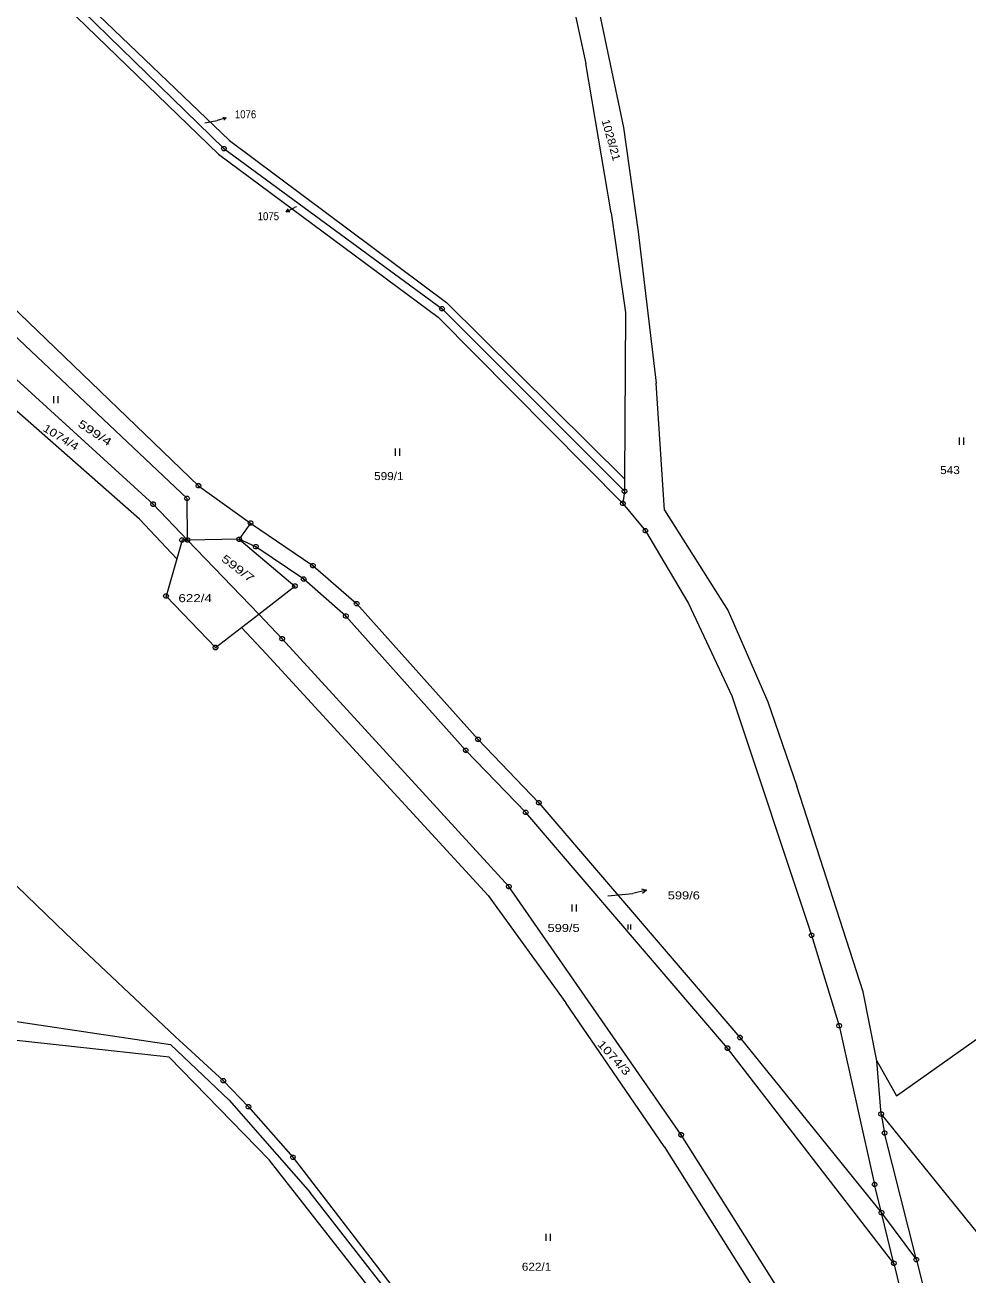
# Model space of a CAD drawing. Extents: x -687390 to -684106, y -954833 to -951648.
# Drawn here: x -686876.1 to -686675.9, y -953282.2 to -953016.7 of the extents above; entities that cross this region are included whole.
import ezdxf
from ezdxf.enums import TextEntityAlignment as Align

# ---------------------------------------------------------------- set-up
doc = ezdxf.new("R2010")
doc.units = 0
doc.header["$LTSCALE"] = 0.68
for name, color, linetype, lineweight in [('1', 7, 'Continuous', 13), ('3', 7, 'Continuous', 13), ('7', 7, 'Continuous', 13), ('8', 7, 'Continuous', 13)]:
    doc.layers.add(name, color=color, linetype=linetype, lineweight=lineweight)
doc.layers.add('2', color=7, linetype='Continuous')

msp = doc.modelspace()

# ---------------------------------------------------------------- linework, layer by layer
at = {"layer": '1'}
for p, q in [((-686764.18, -952991.34), (-686757.06, -953024.89)), ((-686751.65, -953056.55), (-686757.06, -953024.89)), ((-686751.65, -953056.55), (-686748.65, -953077.73)), ((-686745.94, -953060.65), (-686742.13, -953092.77)), ((-686786.65, -953075.62), (-686748.8, -953113.06)), ((-686878.63, -953082.32), (-686841.73, -953117.26)), ((-686848.93, -953118.48), (-686882.52, -953087.82)), ((-686851.84, -953121.63), (-686885.49, -953092.02)), ((-686740.36, -953119.73), (-686742.13, -953092.77)), ((-686841.63, -953126.08), (-686848.93, -953118.48)), ((-686851.84, -953121.63), (-686843.92, -953130.06)), ((-686826.51, -953141.84), (-686841.63, -953126.08)), ((-686826.51, -953141.84), (-686818.81, -953135.86)), ((-686826.51, -953141.84), (-686821.51, -953147.06)), ((-686830.2, -953144.68), (-686824.95, -953150.28)), ((-686777.81, -953201.6), (-686824.95, -953150.28)), ((-686718.37, -953160.43), (-686712.21, -953178.37)), ((-686691.08, -953244.15), (-686578.63, -953164.25)), ((-686698.16, -953222.08), (-686712.21, -953178.37)), ((-686897.44, -953180.91), (-686867.52, -953209.56)), ((-686777.81, -953201.6), (-686761.29, -953224.39)), ((-686844.28, -953231.53), (-686867.52, -953209.56)), ((-686695.24, -953236.73), (-686698.16, -953222.08)), ((-686740.37, -953254.88), (-686761.29, -953224.39)), ((-686834.02, -953240.95), (-686844.28, -953231.53)), ((-686845.52, -953235.93), (-686824.32, -953257.77)), ((-686694.31, -953248.02), (-686693.59, -953252.06)), ((-686686.85, -953278.95), (-686693.59, -953252.06)), ((-686740.37, -953254.88), (-686675.95, -953357.39)), ((-686781.85, -953311.83), (-686824.32, -953257.77)), ((-686694.24, -953268.98), (-686695.71, -953262.97)), ((-686773.57, -953318.57), (-686815.59, -953264.66)), ((-686694.24, -953268.98), (-686686.85, -953278.95)), ((-686691.61, -953279.73), (-686694.24, -953268.98)), ((-686686.85, -953278.95), (-686682.37, -953296.8))]:
    msp.add_line(p, q, dxfattribs=at)
for points in [[(-686903.71, -952971.16), (-686874.76, -953003.02), (-686833.89, -953042.95), (-686787.58, -953076.97), (-686748.81, -953115.73), (-686749.19, -953118.31), (-686744.38, -953124.12), (-686735.23, -953139.57), (-686726.05, -953159.19), (-686709.09, -953210.04), (-686703.22, -953229.26), (-686695.71, -953262.97)], [(-686757.01, -953000.39), (-686749.02, -953038.47), (-686745.94, -953060.65)], [(-686876.02, -953004.42), (-686835.02, -953044.1), (-686788.37, -953078.75), (-686749.19, -953118.31)], [(-686868.78, -953006.67), (-686832.75, -953041.23), (-686786.65, -953075.62)], [(-686929.03, -953026.05), (-686928.66, -953028.62), (-686839.29, -953114.56), (-686828.23, -953122.48), (-686830.67, -953125.93)], [(-686748.65, -953077.73), (-686748.8, -953113.06), (-686748.81, -953115.73)], [(-686830.67, -953125.93), (-686841.63, -953126.08), (-686841.73, -953117.26)], [(-686740.36, -953119.73), (-686726.84, -953141.16), (-686718.37, -953160.43)], [(-686828.23, -953122.48), (-686815, -953131.52), (-686805.71, -953139.6), (-686779.94, -953168.43), (-686767.01, -953181.9), (-686724.31, -953231.77), (-686694.24, -953268.98)], [(-686841.63, -953126.08), (-686842.79, -953126.1), (-686843.92, -953130.06), (-686846.19, -953137.99), (-686835.68, -953148.93), (-686830.2, -953144.68), (-686826.51, -953141.84)], [(-686691.61, -953279.73), (-686726.95, -953234.04), (-686769.81, -953183.96), (-686782.54, -953170.76), (-686808.01, -953142.23), (-686816.95, -953134.39), (-686827.13, -953127.51), (-686830.67, -953125.93), (-686818.81, -953135.86)], [(-686691.61, -953279.73), (-686685.79, -953303.59), (-686677.39, -953346.66), (-686736.8, -953252.45), (-686773.39, -953199.71), (-686821.51, -953147.06)], [(-686845.52, -953235.93), (-686887.1, -953231.37), (-686910.01, -953225.72), (-686942.38, -953198.97)], [(-686907.28, -953222.77), (-686897.88, -953225.38), (-686845.22, -953233.23), (-686832.78, -953245.07), (-686815.59, -953264.66)], [(-686694.31, -953248.02), (-686695.24, -953236.73), (-686691.08, -953244.15)], [(-686834.02, -953240.95), (-686828.66, -953246.47), (-686819.24, -953257.21), (-686798.48, -953284.2), (-686785.18, -953302.55), (-686773.57, -953318.57)], [(-686694.31, -953248.02), (-686654.73, -953296.99), (-686579.98, -953373.97), (-686534.21, -953420.02), (-686500.91, -953457.57), (-686468.1, -953494.74)]]:
    msp.add_lwpolyline(points, dxfattribs=at)
at = {"layer": '3'}
for p, q in [((-686870.07, -953095.51), (-686870.07, -953097.01)), ((-686869.07, -953097.01), (-686869.07, -953095.51)), ((-686677.79, -953104.33), (-686677.79, -953105.83)), ((-686676.79, -953105.83), (-686676.79, -953104.33)), ((-686797.54, -953106.67), (-686797.54, -953108.17)), ((-686796.54, -953108.17), (-686796.54, -953106.67)), ((-686760.01, -953203.49), (-686760.01, -953204.99)), ((-686759.01, -953204.99), (-686759.01, -953203.49)), ((-686748.155, -953207.785), (-686748.155, -953208.79)), ((-686747.485, -953208.79), (-686747.485, -953207.785)), ((-686765.51, -953273.43), (-686765.51, -953274.93)), ((-686764.51, -953274.93), (-686764.51, -953273.43))]:
    msp.add_line(p, q, dxfattribs=at)
at = {"layer": '7'}
for p, q in [((-686837.93, -953037.43), (-686835.33, -953036.99)), ((-686833.413, -953036.385), (-686835.33, -953036.99)), ((-686820.653, -953056.376), (-686818.88, -953055.43)), ((-686818.55, -953055.3), (-686818.88, -953055.43)), ((-686752.35, -953201.64), (-686747.08, -953201.14)), ((-686744.164, -953200.437), (-686747.08, -953201.14))]:
    msp.add_line(p, q, dxfattribs=at)
for points in [[(-686834.153, -953036.267), (-686833.413, -953036.385), (-686833.951, -953036.906)], [(-686819.904, -953056.356), (-686820.653, -953056.376), (-686820.22, -953055.765)], [(-686745.253, -953200.185), (-686744.164, -953200.437), (-686745.019, -953201.157)]]:
    msp.add_lwpolyline(points, dxfattribs=at)
at = {"layer": '8'}
for p, q in [((-686834.01, -953042.95), (-686833.77, -953042.95)), ((-686787.7, -953076.97), (-686787.46, -953076.97)), ((-686839.41, -953114.56), (-686839.17, -953114.56)), ((-686841.85, -953117.26), (-686841.61, -953117.26)), ((-686748.93, -953115.73), (-686748.69, -953115.73)), ((-686849.05, -953118.48), (-686848.81, -953118.48)), ((-686749.31, -953118.31), (-686749.07, -953118.31)), ((-686828.35, -953122.48), (-686828.11, -953122.48)), ((-686744.5, -953124.12), (-686744.26, -953124.12)), ((-686842.91, -953126.1), (-686842.67, -953126.1)), ((-686841.75, -953126.08), (-686841.51, -953126.08)), ((-686830.79, -953125.93), (-686830.55, -953125.93)), ((-686827.25, -953127.51), (-686827.01, -953127.51)), ((-686815.12, -953131.52), (-686814.88, -953131.52)), ((-686818.93, -953135.86), (-686818.69, -953135.86)), ((-686817.07, -953134.39), (-686816.83, -953134.39)), ((-686846.31, -953137.99), (-686846.07, -953137.99)), ((-686805.83, -953139.6), (-686805.59, -953139.6)), ((-686808.13, -953142.23), (-686807.89, -953142.23)), ((-686821.63, -953147.06), (-686821.39, -953147.06)), ((-686835.8, -953148.93), (-686835.56, -953148.93)), ((-686782.66, -953170.76), (-686782.42, -953170.76)), ((-686780.06, -953168.43), (-686779.82, -953168.43)), ((-686769.93, -953183.96), (-686769.69, -953183.96)), ((-686767.13, -953181.9), (-686766.89, -953181.9)), ((-686773.51, -953199.71), (-686773.27, -953199.71)), ((-686709.21, -953210.04), (-686708.97, -953210.04)), ((-686703.34, -953229.26), (-686703.1, -953229.26)), ((-686724.43, -953231.77), (-686724.19, -953231.77)), ((-686727.07, -953234.04), (-686726.83, -953234.04)), ((-686834.14, -953240.95), (-686833.9, -953240.95)), ((-686828.78, -953246.47), (-686828.54, -953246.47)), ((-686694.43, -953248.02), (-686694.19, -953248.02)), ((-686736.92, -953252.45), (-686736.68, -953252.45)), ((-686693.71, -953252.06), (-686693.47, -953252.06)), ((-686819.36, -953257.21), (-686819.12, -953257.21)), ((-686695.83, -953262.97), (-686695.59, -953262.97)), ((-686694.36, -953268.98), (-686694.12, -953268.98)), ((-686691.73, -953279.73), (-686691.49, -953279.73)), ((-686686.97, -953278.95), (-686686.73, -953278.95))]:
    msp.add_line(p, q, dxfattribs=at)
for points in [[(-686833.74, -953042.47), (-686833.49, -953042.65), (-686833.39, -953042.94), (-686833.49, -953043.23), (-686833.74, -953043.41), (-686834.05, -953043.41), (-686834.3, -953043.23), (-686834.4, -953042.94), (-686834.3, -953042.65), (-686834.05, -953042.47)], [(-686787.43, -953076.49), (-686787.18, -953076.67), (-686787.08, -953076.96), (-686787.18, -953077.25), (-686787.43, -953077.43), (-686787.74, -953077.43), (-686787.99, -953077.25), (-686788.09, -953076.96), (-686787.99, -953076.67), (-686787.74, -953076.49)], [(-686839.14, -953114.08), (-686838.89, -953114.26), (-686838.79, -953114.55), (-686838.89, -953114.84), (-686839.14, -953115.02), (-686839.45, -953115.02), (-686839.7, -953114.84), (-686839.8, -953114.55), (-686839.7, -953114.26), (-686839.45, -953114.08)], [(-686748.66, -953115.25), (-686748.41, -953115.43), (-686748.31, -953115.72), (-686748.41, -953116.01), (-686748.66, -953116.19), (-686748.97, -953116.19), (-686749.22, -953116.01), (-686749.32, -953115.72), (-686749.22, -953115.43), (-686748.97, -953115.25)], [(-686841.58, -953116.78), (-686841.33, -953116.96), (-686841.23, -953117.25), (-686841.33, -953117.54), (-686841.58, -953117.72), (-686841.89, -953117.72), (-686842.14, -953117.54), (-686842.24, -953117.25), (-686842.14, -953116.96), (-686841.89, -953116.78)], [(-686749.04, -953117.83), (-686748.79, -953118.01), (-686748.69, -953118.3), (-686748.79, -953118.59), (-686749.04, -953118.77), (-686749.35, -953118.77), (-686749.6, -953118.59), (-686749.7, -953118.3), (-686749.6, -953118.01), (-686749.35, -953117.83)], [(-686848.78, -953118), (-686848.53, -953118.18), (-686848.43, -953118.47), (-686848.53, -953118.76), (-686848.78, -953118.94), (-686849.09, -953118.94), (-686849.34, -953118.76), (-686849.44, -953118.47), (-686849.34, -953118.18), (-686849.09, -953118)], [(-686828.08, -953122), (-686827.83, -953122.18), (-686827.73, -953122.47), (-686827.83, -953122.76), (-686828.08, -953122.94), (-686828.39, -953122.94), (-686828.64, -953122.76), (-686828.74, -953122.47), (-686828.64, -953122.18), (-686828.39, -953122)], [(-686842.64, -953125.62), (-686842.39, -953125.8), (-686842.29, -953126.09), (-686842.39, -953126.38), (-686842.64, -953126.56), (-686842.95, -953126.56), (-686843.2, -953126.38), (-686843.3, -953126.09), (-686843.2, -953125.8), (-686842.95, -953125.62)], [(-686841.48, -953125.6), (-686841.23, -953125.78), (-686841.13, -953126.07), (-686841.23, -953126.36), (-686841.48, -953126.54), (-686841.79, -953126.54), (-686842.04, -953126.36), (-686842.14, -953126.07), (-686842.04, -953125.78), (-686841.79, -953125.6)], [(-686830.52, -953125.45), (-686830.27, -953125.63), (-686830.17, -953125.92), (-686830.27, -953126.21), (-686830.52, -953126.39), (-686830.83, -953126.39), (-686831.08, -953126.21), (-686831.18, -953125.92), (-686831.08, -953125.63), (-686830.83, -953125.45)], [(-686744.23, -953123.64), (-686743.98, -953123.82), (-686743.88, -953124.11), (-686743.98, -953124.4), (-686744.23, -953124.58), (-686744.54, -953124.58), (-686744.79, -953124.4), (-686744.89, -953124.11), (-686744.79, -953123.82), (-686744.54, -953123.64)], [(-686826.98, -953127.03), (-686826.73, -953127.21), (-686826.63, -953127.5), (-686826.73, -953127.79), (-686826.98, -953127.97), (-686827.29, -953127.97), (-686827.54, -953127.79), (-686827.64, -953127.5), (-686827.54, -953127.21), (-686827.29, -953127.03)], [(-686814.85, -953131.04), (-686814.6, -953131.22), (-686814.5, -953131.51), (-686814.6, -953131.8), (-686814.85, -953131.98), (-686815.16, -953131.98), (-686815.41, -953131.8), (-686815.51, -953131.51), (-686815.41, -953131.22), (-686815.16, -953131.04)], [(-686818.66, -953135.38), (-686818.41, -953135.56), (-686818.31, -953135.85), (-686818.41, -953136.14), (-686818.66, -953136.32), (-686818.97, -953136.32), (-686819.22, -953136.14), (-686819.32, -953135.85), (-686819.22, -953135.56), (-686818.97, -953135.38)], [(-686816.8, -953133.91), (-686816.55, -953134.09), (-686816.45, -953134.38), (-686816.55, -953134.67), (-686816.8, -953134.85), (-686817.11, -953134.85), (-686817.36, -953134.67), (-686817.46, -953134.38), (-686817.36, -953134.09), (-686817.11, -953133.91)], [(-686846.04, -953137.51), (-686845.79, -953137.69), (-686845.69, -953137.98), (-686845.79, -953138.27), (-686846.04, -953138.45), (-686846.35, -953138.45), (-686846.6, -953138.27), (-686846.7, -953137.98), (-686846.6, -953137.69), (-686846.35, -953137.51)], [(-686805.56, -953139.12), (-686805.31, -953139.3), (-686805.21, -953139.59), (-686805.31, -953139.88), (-686805.56, -953140.06), (-686805.87, -953140.06), (-686806.12, -953139.88), (-686806.22, -953139.59), (-686806.12, -953139.3), (-686805.87, -953139.12)], [(-686807.86, -953141.75), (-686807.61, -953141.93), (-686807.51, -953142.22), (-686807.61, -953142.51), (-686807.86, -953142.69), (-686808.17, -953142.69), (-686808.42, -953142.51), (-686808.52, -953142.22), (-686808.42, -953141.93), (-686808.17, -953141.75)], [(-686821.36, -953146.58), (-686821.11, -953146.76), (-686821.01, -953147.05), (-686821.11, -953147.34), (-686821.36, -953147.52), (-686821.67, -953147.52), (-686821.92, -953147.34), (-686822.02, -953147.05), (-686821.92, -953146.76), (-686821.67, -953146.58)], [(-686835.53, -953148.45), (-686835.28, -953148.63), (-686835.18, -953148.92), (-686835.28, -953149.21), (-686835.53, -953149.39), (-686835.84, -953149.39), (-686836.09, -953149.21), (-686836.19, -953148.92), (-686836.09, -953148.63), (-686835.84, -953148.45)], [(-686779.79, -953167.95), (-686779.54, -953168.13), (-686779.44, -953168.42), (-686779.54, -953168.71), (-686779.79, -953168.89), (-686780.1, -953168.89), (-686780.35, -953168.71), (-686780.45, -953168.42), (-686780.35, -953168.13), (-686780.1, -953167.95)], [(-686782.39, -953170.28), (-686782.14, -953170.46), (-686782.04, -953170.75), (-686782.14, -953171.04), (-686782.39, -953171.22), (-686782.7, -953171.22), (-686782.95, -953171.04), (-686783.05, -953170.75), (-686782.95, -953170.46), (-686782.7, -953170.28)], [(-686766.86, -953181.42), (-686766.61, -953181.6), (-686766.51, -953181.89), (-686766.61, -953182.18), (-686766.86, -953182.36), (-686767.17, -953182.36), (-686767.42, -953182.18), (-686767.52, -953181.89), (-686767.42, -953181.6), (-686767.17, -953181.42)], [(-686769.66, -953183.48), (-686769.41, -953183.66), (-686769.31, -953183.95), (-686769.41, -953184.24), (-686769.66, -953184.42), (-686769.97, -953184.42), (-686770.22, -953184.24), (-686770.32, -953183.95), (-686770.22, -953183.66), (-686769.97, -953183.48)], [(-686773.24, -953199.23), (-686772.99, -953199.41), (-686772.89, -953199.7), (-686772.99, -953199.99), (-686773.24, -953200.17), (-686773.55, -953200.17), (-686773.8, -953199.99), (-686773.9, -953199.7), (-686773.8, -953199.41), (-686773.55, -953199.23)], [(-686708.94, -953209.56), (-686708.69, -953209.74), (-686708.59, -953210.03), (-686708.69, -953210.32), (-686708.94, -953210.5), (-686709.25, -953210.5), (-686709.5, -953210.32), (-686709.6, -953210.03), (-686709.5, -953209.74), (-686709.25, -953209.56)], [(-686703.07, -953228.78), (-686702.82, -953228.96), (-686702.72, -953229.25), (-686702.82, -953229.54), (-686703.07, -953229.72), (-686703.38, -953229.72), (-686703.63, -953229.54), (-686703.73, -953229.25), (-686703.63, -953228.96), (-686703.38, -953228.78)], [(-686724.16, -953231.29), (-686723.91, -953231.47), (-686723.81, -953231.76), (-686723.91, -953232.05), (-686724.16, -953232.23), (-686724.47, -953232.23), (-686724.72, -953232.05), (-686724.82, -953231.76), (-686724.72, -953231.47), (-686724.47, -953231.29)], [(-686726.8, -953233.56), (-686726.55, -953233.74), (-686726.45, -953234.03), (-686726.55, -953234.32), (-686726.8, -953234.5), (-686727.11, -953234.5), (-686727.36, -953234.32), (-686727.46, -953234.03), (-686727.36, -953233.74), (-686727.11, -953233.56)], [(-686833.87, -953240.47), (-686833.62, -953240.65), (-686833.52, -953240.94), (-686833.62, -953241.23), (-686833.87, -953241.41), (-686834.18, -953241.41), (-686834.43, -953241.23), (-686834.53, -953240.94), (-686834.43, -953240.65), (-686834.18, -953240.47)], [(-686828.51, -953245.99), (-686828.26, -953246.17), (-686828.16, -953246.46), (-686828.26, -953246.75), (-686828.51, -953246.93), (-686828.82, -953246.93), (-686829.07, -953246.75), (-686829.17, -953246.46), (-686829.07, -953246.17), (-686828.82, -953245.99)], [(-686694.16, -953247.54), (-686693.91, -953247.72), (-686693.81, -953248.01), (-686693.91, -953248.3), (-686694.16, -953248.48), (-686694.47, -953248.48), (-686694.72, -953248.3), (-686694.82, -953248.01), (-686694.72, -953247.72), (-686694.47, -953247.54)], [(-686736.65, -953251.97), (-686736.4, -953252.15), (-686736.3, -953252.44), (-686736.4, -953252.73), (-686736.65, -953252.91), (-686736.96, -953252.91), (-686737.21, -953252.73), (-686737.31, -953252.44), (-686737.21, -953252.15), (-686736.96, -953251.97)], [(-686693.44, -953251.58), (-686693.19, -953251.76), (-686693.09, -953252.05), (-686693.19, -953252.34), (-686693.44, -953252.52), (-686693.75, -953252.52), (-686694, -953252.34), (-686694.1, -953252.05), (-686694, -953251.76), (-686693.75, -953251.58)], [(-686819.09, -953256.73), (-686818.84, -953256.91), (-686818.74, -953257.2), (-686818.84, -953257.49), (-686819.09, -953257.67), (-686819.4, -953257.67), (-686819.65, -953257.49), (-686819.75, -953257.2), (-686819.65, -953256.91), (-686819.4, -953256.73)], [(-686695.56, -953262.49), (-686695.31, -953262.67), (-686695.21, -953262.96), (-686695.31, -953263.25), (-686695.56, -953263.43), (-686695.87, -953263.43), (-686696.12, -953263.25), (-686696.22, -953262.96), (-686696.12, -953262.67), (-686695.87, -953262.49)], [(-686694.09, -953268.5), (-686693.84, -953268.68), (-686693.74, -953268.97), (-686693.84, -953269.26), (-686694.09, -953269.44), (-686694.4, -953269.44), (-686694.65, -953269.26), (-686694.75, -953268.97), (-686694.65, -953268.68), (-686694.4, -953268.5)], [(-686691.46, -953279.25), (-686691.21, -953279.43), (-686691.11, -953279.72), (-686691.21, -953280.01), (-686691.46, -953280.19), (-686691.77, -953280.19), (-686692.02, -953280.01), (-686692.12, -953279.72), (-686692.02, -953279.43), (-686691.77, -953279.25)], [(-686686.7, -953278.47), (-686686.45, -953278.65), (-686686.35, -953278.94), (-686686.45, -953279.23), (-686686.7, -953279.41), (-686687.01, -953279.41), (-686687.26, -953279.23), (-686687.36, -953278.94), (-686687.26, -953278.65), (-686687.01, -953278.47)]]:
    msp.add_lwpolyline(points, close=True, dxfattribs=at)

# ---------------------------------------------------------------- texts
at = {"layer": '2'}
for s, height, width, p in [('1076', 0.1, 0.9, (-686837.884, -953037.43)), ('1075', 0.1, 0.9, (-686818.504, -953055.3)), ('599/1', 1.7, 1.1, (-686802.005, -953113.35)), ('543', 1.7, 1.1, (-686681.785, -953112.08)), ('622/4', 1.7, 1.25, (-686843.566, -953139.28)), ('599/6', 0.1, 1.2, (-686752.322, -953201.64)), ('599/5', 1.7, 1.2, (-686765.175, -953209.34)), ('622/1', 1.7, 1.1, (-686770.636, -953281.3))]:
    msp.add_text(s, height=height, dxfattribs=dict(at, width=width)).set_placement(p)
for s, rotation, width, p in [('1028/21', 285.734, 1.1, (-686753.707, -953036.976)), ('1074/4', 328.419, 1.2, (-686872.511, -953102.801)), ('599/4', 326.529, 1.4, (-686865.084, -953101.822)), ('599/7', 322.919, 1.4, (-686834.631, -953130.386)), ('1074/3', 312.033, 1.3, (-686754.714, -953233.273))]:
    msp.add_text(s, height=1.7, rotation=rotation, dxfattribs=dict(at, width=width)).set_placement(p)
at = {"layer": '7'}
for s, width, p in [('1076', 0.9, (-686831.585, -953036.5)), ('599/6', 1.2, (-686739.645, -953202.42))]:
    msp.add_text(s, height=1.7, dxfattribs=dict(at, width=width)).set_placement(p)
at = {"layer": '7', "width": 0.9}
msp.add_text('1075', height=1.7, dxfattribs=at).set_placement((-686822.186, -953058.15), align=Align.RIGHT)

doc.saveas('drawing.dxf')
